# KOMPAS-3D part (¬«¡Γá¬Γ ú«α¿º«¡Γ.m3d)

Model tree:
1. Эскиз:1
2. Операция выдавливания:1
     Расстояние 1 = 8; Расстояние 2 = 8
3. Эскиз:3
4. Операция выдавливания:3
     Расстояние 1 = 0.5; Расстояние 2 = 8
5. Скругление:2
     Радиус = 0.3
6. Эскиз:10
7. Операция выдавливания:10
     Расстояние 1 = 4; Расстояние 2 = 21

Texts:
  stalker61
  Сплав АЛ8  ГОСТ 1583-93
